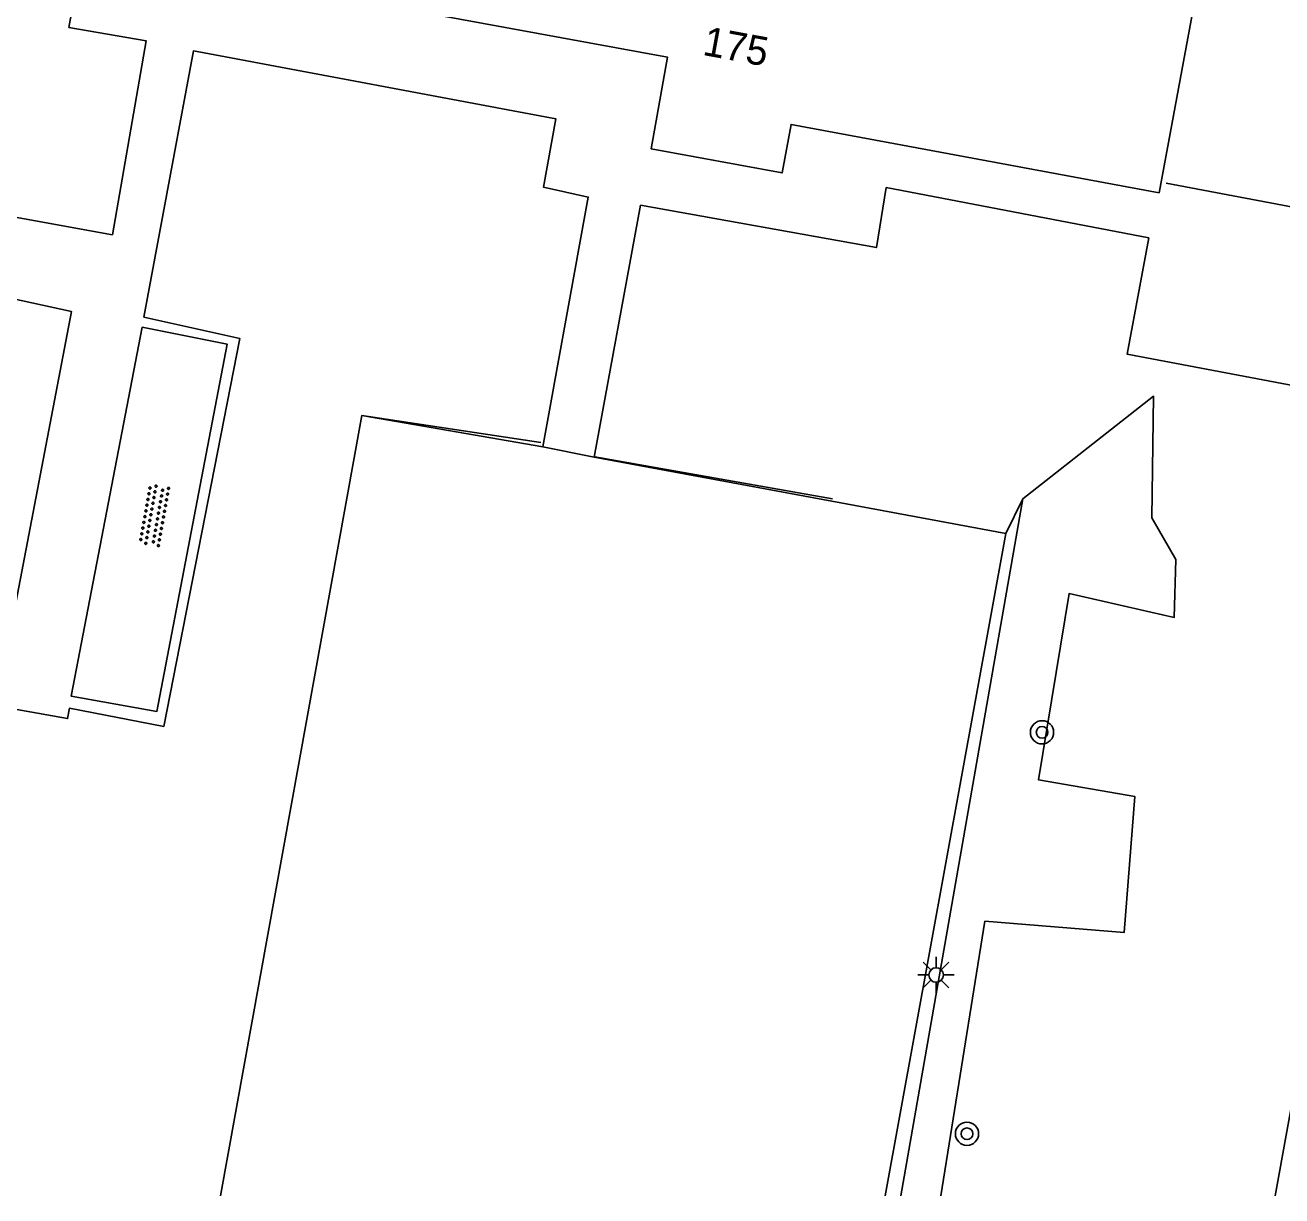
# Model space of a CAD drawing. Extents: x 130998 to 133001, y 398999 to 403002.
# Drawn here: x 132870.83 to 132914.08, y 399000 to 399040.29 of the extents above; entities that cross this region are included whole.
import ezdxf

# ---------------------------------------------------------------- set-up
doc = ezdxf.new("R2010")
doc.units = 0
for name, color, linetype in [('bs-afsc-hekwerk laag', 7, 'Continuous'), ('gg-afsc-erfafscheiding', 7, 'Continuous'), ('gg-afsc-hekwerk', 7, 'Continuous'), ('gg-anno-huisnummerreeks BGT', 7, 'Continuous'), ('gg-bbg-bijgebouw', 7, 'Continuous'), ('gg-bbg-hoofdgebouw', 7, 'Continuous'), ('gg-knt-verharding', 7, 'Continuous'), ('gt-grn-groengrens', 7, 'Continuous'), ('gt-symb-boom', 7, 'Continuous'), ('gt-symb-lichtmast', 7, 'Continuous'), ('gt-symb-overige verharding', 7, 'Continuous')]:
    doc.layers.add(name, color=color, linetype=linetype)

# ---------------------------------------------------------------- blocks, each defined once
blk = doc.blocks.new('gt0-OVH')
at = {"layer": 'gt-symb-overige verharding'}
for points in [[(-0.972, 0.298), (-0.967, 0.308), (-0.965, 0.319), (-0.966, 0.33), (-0.971, 0.34), (-0.978, 0.348), (-0.988, 0.353), (-0.999, 0.355), (-1.01, 0.354), (-1.02, 0.349), (-1.028, 0.342), (-1.033, 0.332), (-1.035, 0.321), (-1.034, 0.31), (-1.029, 0.3), (-1.022, 0.292), (-1.012, 0.287), (-1.001, 0.285), (-0.99, 0.286), (-0.98, 0.291)], [(-0.872, 0.106), (-0.867, 0.116), (-0.865, 0.126), (-0.866, 0.137), (-0.871, 0.147), (-0.878, 0.156), (-0.888, 0.161), (-0.899, 0.163), (-0.91, 0.162), (-0.92, 0.157), (-0.928, 0.15), (-0.933, 0.14), (-0.935, 0.129), (-0.934, 0.118), (-0.929, 0.108), (-0.922, 0.1), (-0.912, 0.095), (-0.901, 0.092), (-0.89, 0.094), (-0.88, 0.098)], [(-0.772, 0.298), (-0.767, 0.308), (-0.765, 0.319), (-0.766, 0.33), (-0.771, 0.34), (-0.778, 0.348), (-0.788, 0.353), (-0.799, 0.355), (-0.81, 0.354), (-0.82, 0.349), (-0.828, 0.342), (-0.833, 0.332), (-0.835, 0.321), (-0.834, 0.31), (-0.829, 0.3), (-0.822, 0.292), (-0.812, 0.287), (-0.801, 0.285), (-0.79, 0.286), (-0.78, 0.291)], [(-0.672, 0.106), (-0.667, 0.116), (-0.665, 0.126), (-0.666, 0.137), (-0.671, 0.147), (-0.678, 0.156), (-0.688, 0.161), (-0.699, 0.163), (-0.71, 0.162), (-0.72, 0.157), (-0.728, 0.15), (-0.733, 0.14), (-0.735, 0.129), (-0.734, 0.118), (-0.729, 0.108), (-0.722, 0.1), (-0.712, 0.095), (-0.701, 0.092), (-0.69, 0.094), (-0.68, 0.098)], [(-0.572, 0.298), (-0.567, 0.308), (-0.565, 0.319), (-0.566, 0.33), (-0.571, 0.34), (-0.578, 0.348), (-0.588, 0.353), (-0.599, 0.355), (-0.61, 0.354), (-0.62, 0.349), (-0.628, 0.342), (-0.633, 0.332), (-0.635, 0.321), (-0.634, 0.31), (-0.629, 0.3), (-0.622, 0.292), (-0.612, 0.287), (-0.601, 0.285), (-0.59, 0.286), (-0.58, 0.291)], [(-0.472, 0.106), (-0.467, 0.116), (-0.465, 0.126), (-0.466, 0.137), (-0.471, 0.147), (-0.478, 0.156), (-0.488, 0.161), (-0.499, 0.163), (-0.51, 0.162), (-0.52, 0.157), (-0.528, 0.15), (-0.533, 0.14), (-0.535, 0.129), (-0.534, 0.118), (-0.529, 0.108), (-0.522, 0.1), (-0.512, 0.095), (-0.501, 0.092), (-0.49, 0.094), (-0.48, 0.098)], [(-0.372, 0.298), (-0.367, 0.308), (-0.365, 0.319), (-0.366, 0.33), (-0.371, 0.34), (-0.378, 0.348), (-0.388, 0.353), (-0.399, 0.355), (-0.41, 0.354), (-0.42, 0.349), (-0.428, 0.342), (-0.433, 0.332), (-0.435, 0.321), (-0.434, 0.31), (-0.429, 0.3), (-0.422, 0.292), (-0.412, 0.287), (-0.401, 0.285), (-0.39, 0.286), (-0.38, 0.291)], [(-0.272, 0.106), (-0.267, 0.116), (-0.265, 0.126), (-0.266, 0.137), (-0.271, 0.147), (-0.278, 0.156), (-0.288, 0.161), (-0.299, 0.163), (-0.31, 0.162), (-0.32, 0.157), (-0.328, 0.15), (-0.333, 0.14), (-0.335, 0.129), (-0.334, 0.118), (-0.329, 0.108), (-0.322, 0.1), (-0.312, 0.095), (-0.301, 0.092), (-0.29, 0.094), (-0.28, 0.098)], [(-0.172, 0.298), (-0.167, 0.308), (-0.165, 0.319), (-0.166, 0.33), (-0.171, 0.34), (-0.178, 0.348), (-0.188, 0.353), (-0.199, 0.355), (-0.21, 0.354), (-0.22, 0.349), (-0.228, 0.342), (-0.233, 0.332), (-0.235, 0.321), (-0.234, 0.31), (-0.229, 0.3), (-0.222, 0.292), (-0.212, 0.287), (-0.201, 0.285), (-0.19, 0.286), (-0.18, 0.291)], [(-0.072, 0.106), (-0.067, 0.116), (-0.065, 0.126), (-0.066, 0.137), (-0.071, 0.147), (-0.078, 0.156), (-0.088, 0.161), (-0.099, 0.163), (-0.11, 0.162), (-0.12, 0.157), (-0.128, 0.15), (-0.133, 0.14), (-0.135, 0.129), (-0.134, 0.118), (-0.129, 0.108), (-0.122, 0.1), (-0.112, 0.095), (-0.101, 0.092), (-0.09, 0.094), (-0.08, 0.098)], [(0.028, 0.298), (0.033, 0.308), (0.035, 0.319), (0.034, 0.33), (0.029, 0.34), (0.022, 0.348), (0.012, 0.353), (0.001, 0.355), (-0.01, 0.354), (-0.02, 0.349), (-0.028, 0.342), (-0.033, 0.332), (-0.035, 0.321), (-0.034, 0.31), (-0.029, 0.3), (-0.022, 0.292), (-0.012, 0.287), (-0.001, 0.285), (0.01, 0.286), (0.02, 0.291)], [(0.128, 0.106), (0.133, 0.116), (0.135, 0.126), (0.134, 0.137), (0.129, 0.147), (0.122, 0.156), (0.112, 0.161), (0.101, 0.163), (0.09, 0.162), (0.08, 0.157), (0.072, 0.15), (0.067, 0.14), (0.065, 0.129), (0.066, 0.118), (0.071, 0.108), (0.078, 0.1), (0.088, 0.095), (0.099, 0.092), (0.11, 0.094), (0.12, 0.098)], [(0.228, 0.298), (0.233, 0.308), (0.235, 0.319), (0.234, 0.33), (0.229, 0.34), (0.222, 0.348), (0.212, 0.353), (0.201, 0.355), (0.19, 0.354), (0.18, 0.349), (0.172, 0.342), (0.167, 0.332), (0.165, 0.321), (0.166, 0.31), (0.171, 0.3), (0.178, 0.292), (0.188, 0.287), (0.199, 0.285), (0.21, 0.286), (0.22, 0.291)], [(0.328, 0.106), (0.333, 0.116), (0.335, 0.126), (0.334, 0.137), (0.329, 0.147), (0.322, 0.156), (0.312, 0.161), (0.301, 0.163), (0.29, 0.162), (0.28, 0.157), (0.272, 0.15), (0.267, 0.14), (0.265, 0.129), (0.266, 0.118), (0.271, 0.108), (0.278, 0.1), (0.288, 0.095), (0.299, 0.092), (0.31, 0.094), (0.32, 0.098)], [(0.428, 0.298), (0.433, 0.308), (0.435, 0.319), (0.434, 0.33), (0.429, 0.34), (0.422, 0.348), (0.412, 0.353), (0.401, 0.355), (0.39, 0.354), (0.38, 0.349), (0.372, 0.342), (0.367, 0.332), (0.365, 0.321), (0.366, 0.31), (0.371, 0.3), (0.378, 0.292), (0.388, 0.287), (0.399, 0.285), (0.41, 0.286), (0.42, 0.291)], [(0.528, 0.106), (0.533, 0.116), (0.535, 0.126), (0.534, 0.137), (0.529, 0.147), (0.522, 0.156), (0.512, 0.161), (0.501, 0.163), (0.49, 0.162), (0.48, 0.157), (0.472, 0.15), (0.467, 0.14), (0.465, 0.129), (0.466, 0.118), (0.471, 0.108), (0.478, 0.1), (0.488, 0.095), (0.499, 0.092), (0.51, 0.094), (0.52, 0.098)], [(0.628, 0.298), (0.633, 0.308), (0.635, 0.319), (0.634, 0.33), (0.629, 0.34), (0.622, 0.348), (0.612, 0.353), (0.601, 0.355), (0.59, 0.354), (0.58, 0.349), (0.572, 0.342), (0.567, 0.332), (0.565, 0.321), (0.566, 0.31), (0.571, 0.3), (0.578, 0.292), (0.588, 0.287), (0.599, 0.285), (0.61, 0.286), (0.62, 0.291)], [(0.728, 0.106), (0.733, 0.116), (0.735, 0.126), (0.734, 0.137), (0.729, 0.147), (0.722, 0.156), (0.712, 0.161), (0.701, 0.163), (0.69, 0.162), (0.68, 0.157), (0.672, 0.15), (0.667, 0.14), (0.665, 0.129), (0.666, 0.118), (0.671, 0.108), (0.678, 0.1), (0.688, 0.095), (0.699, 0.092), (0.71, 0.094), (0.72, 0.098)], [(0.828, 0.298), (0.833, 0.308), (0.835, 0.319), (0.834, 0.33), (0.829, 0.34), (0.822, 0.348), (0.812, 0.353), (0.801, 0.355), (0.79, 0.354), (0.78, 0.349), (0.772, 0.342), (0.767, 0.332), (0.765, 0.321), (0.766, 0.31), (0.771, 0.3), (0.778, 0.292), (0.788, 0.287), (0.799, 0.285), (0.81, 0.286), (0.82, 0.291)], [(0.928, 0.106), (0.933, 0.116), (0.935, 0.126), (0.934, 0.137), (0.929, 0.147), (0.922, 0.156), (0.912, 0.161), (0.901, 0.163), (0.89, 0.162), (0.88, 0.157), (0.872, 0.15), (0.867, 0.14), (0.865, 0.129), (0.866, 0.118), (0.871, 0.108), (0.878, 0.1), (0.888, 0.095), (0.899, 0.092), (0.91, 0.094), (0.92, 0.098)], [(1.028, 0.298), (1.033, 0.308), (1.035, 0.319), (1.034, 0.33), (1.029, 0.34), (1.022, 0.348), (1.012, 0.353), (1.001, 0.355), (0.99, 0.354), (0.98, 0.349), (0.972, 0.342), (0.967, 0.332), (0.965, 0.321), (0.966, 0.31), (0.971, 0.3), (0.978, 0.292), (0.988, 0.287), (0.999, 0.285), (1.01, 0.286), (1.02, 0.291)], [(-0.972, -0.142), (-0.967, -0.132), (-0.965, -0.121), (-0.966, -0.11), (-0.971, -0.1), (-0.978, -0.092), (-0.988, -0.087), (-0.999, -0.085), (-1.01, -0.086), (-1.02, -0.091), (-1.028, -0.098), (-1.033, -0.108), (-1.035, -0.119), (-1.034, -0.13), (-1.029, -0.14), (-1.022, -0.148), (-1.012, -0.153), (-1.001, -0.155), (-0.99, -0.154), (-0.98, -0.149)], [(-0.872, -0.334), (-0.867, -0.324), (-0.865, -0.314), (-0.866, -0.303), (-0.871, -0.293), (-0.878, -0.284), (-0.888, -0.279), (-0.899, -0.277), (-0.91, -0.278), (-0.92, -0.283), (-0.928, -0.29), (-0.933, -0.3), (-0.935, -0.311), (-0.934, -0.322), (-0.929, -0.332), (-0.922, -0.34), (-0.912, -0.345), (-0.901, -0.348), (-0.89, -0.346), (-0.88, -0.342)], [(-0.772, -0.142), (-0.767, -0.132), (-0.765, -0.121), (-0.766, -0.11), (-0.771, -0.1), (-0.778, -0.092), (-0.788, -0.087), (-0.799, -0.085), (-0.81, -0.086), (-0.82, -0.091), (-0.828, -0.098), (-0.833, -0.108), (-0.835, -0.119), (-0.834, -0.13), (-0.829, -0.14), (-0.822, -0.148), (-0.812, -0.153), (-0.801, -0.155), (-0.79, -0.154), (-0.78, -0.149)], [(-0.672, -0.334), (-0.667, -0.324), (-0.665, -0.314), (-0.666, -0.303), (-0.671, -0.293), (-0.678, -0.284), (-0.688, -0.279), (-0.699, -0.277), (-0.71, -0.278), (-0.72, -0.283), (-0.728, -0.29), (-0.733, -0.3), (-0.735, -0.311), (-0.734, -0.322), (-0.729, -0.332), (-0.722, -0.34), (-0.712, -0.345), (-0.701, -0.348), (-0.69, -0.346), (-0.68, -0.342)], [(-0.572, -0.142), (-0.567, -0.132), (-0.565, -0.121), (-0.566, -0.11), (-0.571, -0.1), (-0.578, -0.092), (-0.588, -0.087), (-0.599, -0.085), (-0.61, -0.086), (-0.62, -0.091), (-0.628, -0.098), (-0.633, -0.108), (-0.635, -0.119), (-0.634, -0.13), (-0.629, -0.14), (-0.622, -0.148), (-0.612, -0.153), (-0.601, -0.155), (-0.59, -0.154), (-0.58, -0.149)], [(-0.472, -0.334), (-0.467, -0.324), (-0.465, -0.314), (-0.466, -0.303), (-0.471, -0.293), (-0.478, -0.284), (-0.488, -0.279), (-0.499, -0.277), (-0.51, -0.278), (-0.52, -0.283), (-0.528, -0.29), (-0.533, -0.3), (-0.535, -0.311), (-0.534, -0.322), (-0.529, -0.332), (-0.522, -0.34), (-0.512, -0.345), (-0.501, -0.348), (-0.49, -0.346), (-0.48, -0.342)], [(-0.372, -0.142), (-0.367, -0.132), (-0.365, -0.121), (-0.366, -0.11), (-0.371, -0.1), (-0.378, -0.092), (-0.388, -0.087), (-0.399, -0.085), (-0.41, -0.086), (-0.42, -0.091), (-0.428, -0.098), (-0.433, -0.108), (-0.435, -0.119), (-0.434, -0.13), (-0.429, -0.14), (-0.422, -0.148), (-0.412, -0.153), (-0.401, -0.155), (-0.39, -0.154), (-0.38, -0.149)], [(-0.272, -0.334), (-0.267, -0.324), (-0.265, -0.314), (-0.266, -0.303), (-0.271, -0.293), (-0.278, -0.284), (-0.288, -0.279), (-0.299, -0.277), (-0.31, -0.278), (-0.32, -0.283), (-0.328, -0.29), (-0.333, -0.3), (-0.335, -0.311), (-0.334, -0.322), (-0.329, -0.332), (-0.322, -0.34), (-0.312, -0.345), (-0.301, -0.348), (-0.29, -0.346), (-0.28, -0.342)], [(-0.172, -0.142), (-0.167, -0.132), (-0.165, -0.121), (-0.166, -0.11), (-0.171, -0.1), (-0.178, -0.092), (-0.188, -0.087), (-0.199, -0.085), (-0.21, -0.086), (-0.22, -0.091), (-0.228, -0.098), (-0.233, -0.108), (-0.235, -0.119), (-0.234, -0.13), (-0.229, -0.14), (-0.222, -0.148), (-0.212, -0.153), (-0.201, -0.155), (-0.19, -0.154), (-0.18, -0.149)], [(-0.072, -0.334), (-0.067, -0.324), (-0.065, -0.314), (-0.066, -0.303), (-0.071, -0.293), (-0.078, -0.284), (-0.088, -0.279), (-0.099, -0.277), (-0.11, -0.278), (-0.12, -0.283), (-0.128, -0.29), (-0.133, -0.3), (-0.135, -0.311), (-0.134, -0.322), (-0.129, -0.332), (-0.122, -0.34), (-0.112, -0.345), (-0.101, -0.348), (-0.09, -0.346), (-0.08, -0.342)], [(0.028, -0.142), (0.033, -0.132), (0.035, -0.121), (0.034, -0.11), (0.029, -0.1), (0.022, -0.092), (0.012, -0.087), (0.001, -0.085), (-0.01, -0.086), (-0.02, -0.091), (-0.028, -0.098), (-0.033, -0.108), (-0.035, -0.119), (-0.034, -0.13), (-0.029, -0.14), (-0.022, -0.148), (-0.012, -0.153), (-0.001, -0.155), (0.01, -0.154), (0.02, -0.149)], [(0.128, -0.334), (0.133, -0.324), (0.135, -0.314), (0.134, -0.303), (0.129, -0.293), (0.122, -0.284), (0.112, -0.279), (0.101, -0.277), (0.09, -0.278), (0.08, -0.283), (0.072, -0.29), (0.067, -0.3), (0.065, -0.311), (0.066, -0.322), (0.071, -0.332), (0.078, -0.34), (0.088, -0.345), (0.099, -0.348), (0.11, -0.346), (0.12, -0.342)], [(0.228, -0.142), (0.233, -0.132), (0.235, -0.121), (0.234, -0.11), (0.229, -0.1), (0.222, -0.092), (0.212, -0.087), (0.201, -0.085), (0.19, -0.086), (0.18, -0.091), (0.172, -0.098), (0.167, -0.108), (0.165, -0.119), (0.166, -0.13), (0.171, -0.14), (0.178, -0.148), (0.188, -0.153), (0.199, -0.155), (0.21, -0.154), (0.22, -0.149)], [(0.328, -0.334), (0.333, -0.324), (0.335, -0.314), (0.334, -0.303), (0.329, -0.293), (0.322, -0.284), (0.312, -0.279), (0.301, -0.277), (0.29, -0.278), (0.28, -0.283), (0.272, -0.29), (0.267, -0.3), (0.265, -0.311), (0.266, -0.322), (0.271, -0.332), (0.278, -0.34), (0.288, -0.345), (0.299, -0.348), (0.31, -0.346), (0.32, -0.342)], [(0.428, -0.142), (0.433, -0.132), (0.435, -0.121), (0.434, -0.11), (0.429, -0.1), (0.422, -0.092), (0.412, -0.087), (0.401, -0.085), (0.39, -0.086), (0.38, -0.091), (0.372, -0.098), (0.367, -0.108), (0.365, -0.119), (0.366, -0.13), (0.371, -0.14), (0.378, -0.148), (0.388, -0.153), (0.399, -0.155), (0.41, -0.154), (0.42, -0.149)], [(0.528, -0.334), (0.533, -0.324), (0.535, -0.314), (0.534, -0.303), (0.529, -0.293), (0.522, -0.284), (0.512, -0.279), (0.501, -0.277), (0.49, -0.278), (0.48, -0.283), (0.472, -0.29), (0.467, -0.3), (0.465, -0.311), (0.466, -0.322), (0.471, -0.332), (0.478, -0.34), (0.488, -0.345), (0.499, -0.348), (0.51, -0.346), (0.52, -0.342)], [(0.628, -0.142), (0.633, -0.132), (0.635, -0.121), (0.634, -0.11), (0.629, -0.1), (0.622, -0.092), (0.612, -0.087), (0.601, -0.085), (0.59, -0.086), (0.58, -0.091), (0.572, -0.098), (0.567, -0.108), (0.565, -0.119), (0.566, -0.13), (0.571, -0.14), (0.578, -0.148), (0.588, -0.153), (0.599, -0.155), (0.61, -0.154), (0.62, -0.149)], [(0.728, -0.334), (0.733, -0.324), (0.735, -0.314), (0.734, -0.303), (0.729, -0.293), (0.722, -0.284), (0.712, -0.279), (0.701, -0.277), (0.69, -0.278), (0.68, -0.283), (0.672, -0.29), (0.667, -0.3), (0.665, -0.311), (0.666, -0.322), (0.671, -0.332), (0.678, -0.34), (0.688, -0.345), (0.699, -0.348), (0.71, -0.346), (0.72, -0.342)], [(0.828, -0.142), (0.833, -0.132), (0.835, -0.121), (0.834, -0.11), (0.829, -0.1), (0.822, -0.092), (0.812, -0.087), (0.801, -0.085), (0.79, -0.086), (0.78, -0.091), (0.772, -0.098), (0.767, -0.108), (0.765, -0.119), (0.766, -0.13), (0.771, -0.14), (0.778, -0.148), (0.788, -0.153), (0.799, -0.155), (0.81, -0.154), (0.82, -0.149)], [(0.928, -0.334), (0.933, -0.324), (0.935, -0.314), (0.934, -0.303), (0.929, -0.293), (0.922, -0.284), (0.912, -0.279), (0.901, -0.277), (0.89, -0.278), (0.88, -0.283), (0.872, -0.29), (0.867, -0.3), (0.865, -0.311), (0.866, -0.322), (0.871, -0.332), (0.878, -0.34), (0.888, -0.345), (0.899, -0.348), (0.91, -0.346), (0.92, -0.342)], [(1.028, -0.142), (1.033, -0.132), (1.035, -0.121), (1.034, -0.11), (1.029, -0.1), (1.022, -0.092), (1.012, -0.087), (1.001, -0.085), (0.99, -0.086), (0.98, -0.091), (0.972, -0.098), (0.967, -0.108), (0.965, -0.119), (0.966, -0.13), (0.971, -0.14), (0.978, -0.148), (0.988, -0.153), (0.999, -0.155), (1.01, -0.154), (1.02, -0.149)]]:
    blk.add_lwpolyline(points, close=True, dxfattribs=at)
blk = doc.blocks.new('gt0-LMAST')
at = {"layer": 'gt-symb-lichtmast'}
for p, q in [((-0.182, 0.173), (-0.447, 0.438)), ((-0.005, 0.246), (-0.005, 0.621)), ((0.172, 0.173), (0.437, 0.438)), ((-0.255, -0.004), (-0.63, -0.004)), ((-0.182, -0.181), (-0.447, -0.446)), ((-0.005, -0.254), (-0.005, -0.629)), ((0.437, -0.446), (0.172, -0.181)), ((0.245, -0.004), (0.62, -0.004))]:
    blk.add_line(p, q, dxfattribs=at)
blk.add_circle((-0.005, -0.004), 0.25, dxfattribs=at)
blk = doc.blocks.new('gt0-BOOM')
at = {"layer": 'gt-symb-boom'}
for radius in [0.4, 0.2]:
    blk.add_circle((0, 0), radius, dxfattribs=at)

msp = doc.modelspace()

# ---------------------------------------------------------------- linework, layer by layer
at = {"layer": 'bs-afsc-hekwerk laag'}
for p, q in [((132890.434, 399025.439), (132898.61, 399023.983)), ((132900.967, 399000), (132905.166, 399023.989))]:
    msp.add_line(p, q, dxfattribs=at)
msp.add_lwpolyline([(132877.554, 399000), (132882.409, 399026.851), (132888.574, 399025.923)], dxfattribs=at)
at = {"layer": 'gg-afsc-erfafscheiding'}
msp.add_line((132910.095, 399034.847), (132914.524, 399034.01), dxfattribs=at)
at = {"layer": 'gg-afsc-hekwerk'}
msp.add_line((132890.414, 399025.426), (132898.596, 399023.908), dxfattribs=at)
msp.add_lwpolyline([(132877.554, 399000), (132882.409, 399026.851), (132888.644, 399025.775)], dxfattribs=at)
at = {"layer": 'gg-bbg-bijgebouw'}
msp.add_lwpolyline([(132869.82, 399016.87), (132872.42, 399030.44), (132867.58, 399031.49)], dxfattribs=at)
at = {"layer": 'gg-bbg-hoofdgebouw'}
msp.add_lwpolyline([(132875.005, 399042.482), (132877.089, 399053.714), (132899.296, 399049.645), (132899.316, 399049.753), (132912.235, 399047.351), (132909.857, 399034.523), (132897.19, 399036.875), (132896.882, 399035.203), (132892.375, 399036.033), (132892.938, 399039.188), (132875.005, 399042.482)], dxfattribs=at)
at = {"layer": 'gg-knt-verharding'}
for p, q in [((132888.644, 399025.775), (132890.414, 399025.426)), ((132898.596, 399023.908), (132904.579, 399022.798)), ((132900.432, 399000), (132904.579, 399022.798))]:
    msp.add_line(p, q, dxfattribs=at)
for points in [[(132866.938, 399034.326), (132873.827, 399033.076), (132874.994, 399039.751), (132872.334, 399040.215), (132875.182, 399055.758), (132868.492, 399056.969), (132868.943, 399059.455)], [(132888.644, 399025.775), (132890.208, 399034.376), (132888.673, 399034.71), (132889.098, 399037.066), (132876.619, 399039.402), (132874.913, 399030.244), (132878.22, 399029.501), (132875.596, 399016.159), (132872.348, 399016.779), (132872.289, 399016.424), (132869.82, 399016.87)], [(132913.849, 399000), (132918.767, 399027.08), (132908.756, 399028.972), (132909.503, 399032.971), (132900.468, 399034.7), (132900.127, 399032.634), (132892.012, 399034.095), (132890.414, 399025.426)], [(132874.851, 399029.893), (132877.777, 399029.315), (132875.36, 399016.675), (132872.414, 399017.203), (132874.851, 399029.893)]]:
    msp.add_lwpolyline(points, dxfattribs=at)
at = {"layer": 'gt-grn-groengrens'}
msp.add_lwpolyline([(132902.348, 399000), (132903.862, 399009.45), (132908.66, 399009.067), (132909.018, 399013.749), (132905.712, 399014.317), (132906.759, 399020.726), (132910.379, 399019.907), (132910.428, 399021.9), (132909.611, 399023.339), (132909.67, 399027.522), (132905.166, 399023.989), (132904.579, 399022.798)], dxfattribs=at)

# ---------------------------------------------------------------- block references
at = {"layer": 'gt-symb-boom'}
for p in [(132905.828, 399015.953), (132903.245, 399002.138)]:
    msp.add_blockref('gt0-BOOM', p, dxfattribs=at)
at = {"layer": 'gt-symb-lichtmast'}
msp.add_blockref('gt0-LMAST', (132902.188, 399007.606), dxfattribs=at)
at = {"layer": 'gt-symb-overige verharding', "rotation": -100.14079314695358}
msp.add_blockref('gt0-OVH', (132875.272, 399023.42), dxfattribs=at)

# ---------------------------------------------------------------- texts
at = {"layer": 'gg-anno-huisnummerreeks BGT'}
msp.add_text('175', height=1, rotation=349.6, dxfattribs=at).set_placement((132894.11, 399039.271))

doc.saveas('drawing.dxf')
